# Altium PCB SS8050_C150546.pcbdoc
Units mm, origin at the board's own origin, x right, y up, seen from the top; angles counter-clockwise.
Board outline 17.59 x 16.55 mm, 2 copper layers (Top Layer, Bottom Layer), stack 0 mm thick; 1 components, 0 nets, 3 pads, 0 vias.
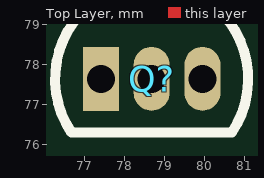
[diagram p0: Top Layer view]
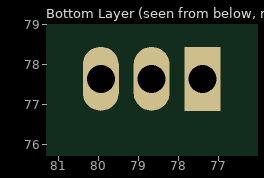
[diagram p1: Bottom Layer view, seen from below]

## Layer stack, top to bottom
Top Layer: signal copper (thickness not stored)
Bottom Layer: signal copper (thickness not stored)

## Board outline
87.436,69.85 69.85,69.85 69.85,86.4 87.436,86.4

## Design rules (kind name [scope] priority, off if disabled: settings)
PasteMaskExpansion "Paste Mask Expansion" [All] p1: expansion=0
SolderMaskExpansion "Solder Mask Expansion" [IsVia] p1: expansion=-25.4 istentingtop=TRUE
SolderMaskExpansion "Solder Mask Expansion" [All] p2: expansion=0.051 istentingtop=FALSE

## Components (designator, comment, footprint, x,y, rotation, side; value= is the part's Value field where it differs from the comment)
Q? "SS8050(RANGE:160-300)" TO-92-3_L5.1-W4.1-P1.27-L 78.673,77.64 r0 top

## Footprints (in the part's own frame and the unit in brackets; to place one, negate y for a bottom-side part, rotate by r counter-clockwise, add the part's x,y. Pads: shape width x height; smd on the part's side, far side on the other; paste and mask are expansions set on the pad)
TO-92-3_L5.1-W4.1-P1.27-L [mm]
  rect 0.9x1.6 hole 0.7: 1(-1.27,0)
  oval 0.9x1.6 hole 0.7: 2(0,0) 3(1.27,0)
  silkscreen extent -2.41,-1.35 2.41,2.41

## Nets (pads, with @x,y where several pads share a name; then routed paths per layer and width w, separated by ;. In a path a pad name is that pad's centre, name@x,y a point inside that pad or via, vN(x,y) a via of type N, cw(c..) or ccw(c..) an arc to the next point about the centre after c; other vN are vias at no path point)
pads on no net: Q?.1 Q?.2 Q?.3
